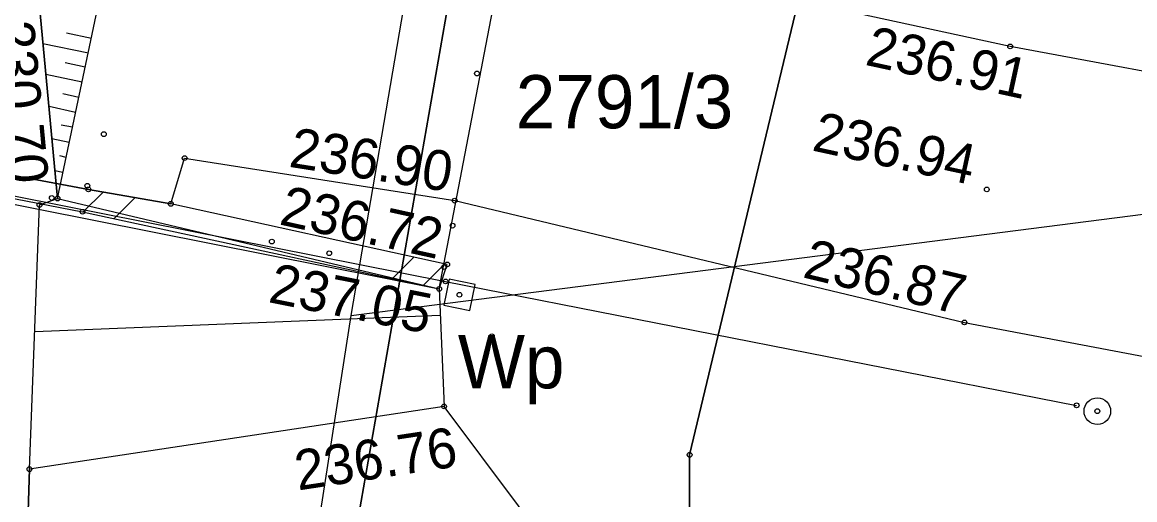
# Model space of a CAD drawing. Extents: x 6596400 to 6597200, y 5539751 to 5540251.
# Drawn here: x 6596740.59 to 6596761.51, y 5540079.28 to 5540088.25 of the extents above; entities that cross this region are included whole.
import ezdxf

# ---------------------------------------------------------------- set-up
doc = ezdxf.new("R2010")
doc.units = 0
for name, color, linetype in [('000 Inne (niezydentyfikowane)', 7, 'Continuous'), ('140-Punkty robocze', 7, 'Continuous'), ('203-punkt graniczny', 7, 'Continuous'), ('210-oznaczenie konturu użytku gruntowego', 7, 'Continuous'), ('211-numer działki ewidencyjnej', 7, 'Continuous'), ('218-kontur użytku gruntowego', 7, 'Continuous'), ('219-działka ewidencyjna', 7, 'Continuous'), ('bariera ochronna', 7, 'Continuous'), ('jezdnia', 7, 'Continuous'), ('Linia obszaru zagospodarowania terenu', 7, 'Continuous'), ('most', 7, 'Continuous'), ('pikieta sztuczna', 7, 'Continuous'), ('pikieta sztuczna-Atr2', 7, 'Continuous'), ('przewód telekomunikacyjny napowietrzny', 7, 'Continuous'), ('skarpa nieumocniona', 7, 'Continuous'), ('skarpa umocniona', 7, 'Continuous'), ('woda płynąca', 7, 'Continuous'), ('właz do komory lub kanału - kwadratowy', 7, 'Continuous'), ('właz do komory lub kanału - okrągły', 7, 'Continuous'), ('ściana oporowa (poligon)', 7, 'Continuous')]:
    doc.layers.add(name, color=color, linetype=linetype)

# ---------------------------------------------------------------- blocks, each defined once
blk = doc.blocks.new('203')
blk.add_circle((0, 0), 0.045)
blk = doc.blocks.new('SUTP')
for p, q in [((0, 0), (0.866, 0.5)), ((9.232, 0), (8.366, 0.5)), ((0, 0), (9.232, 0)), ((1.866, -0.5), (1, 0)), ((7.366, -0.5), (8.232, 0))]:
    blk.add_line(p, q)
blk = doc.blocks.new('US22A')
blk.add_lwpolyline([(-0.25, -0.25), (0.25, -0.25), (0.25, 0.25), (-0.25, 0.25)], close=True)
blk = doc.blocks.new('US22')
blk.add_circle((0, 0), 0.25)
blk = doc.blocks.new('PIKIETA')
blk.add_circle((0, 0), 0.045)
blk = doc.blocks.new('PW01')
blk.add_circle((0, 0), 0.045)

msp = doc.modelspace()

# ---------------------------------------------------------------- linework, layer by layer
at = {"layer": '000 Inne (niezydentyfikowane)'}
for points in [[(6596741.89, 5540087.95), (6596741.42, 5540088.05)], [(6596741.83, 5540087.67), (6596740.97, 5540087.85)], [(6596741.77, 5540087.41), (6596741.39, 5540087.49)], [(6596741.71, 5540087.13), (6596741.03, 5540087.27)], [(6596741.65, 5540086.84), (6596741.35, 5540086.91)], [(6596741.59, 5540086.56), (6596741.09, 5540086.67)], [(6596741.53, 5540086.28), (6596741.32, 5540086.32)], [(6596741.47, 5540085.99), (6596741.14, 5540086.06)], [(6596741.41, 5540085.71), (6596741.29, 5540085.74)], [(6596741.35, 5540085.43), (6596741.2, 5540085.46)], [(6596748.45, 5540082.74), (6596740.82, 5540082.43)]]:
    msp.add_lwpolyline(points, dxfattribs=at)
at = {"layer": '218-kontur użytku gruntowego'}
for points in [[(6596745.91, 5540073.23), (6596750.12, 5540097.31)], [(6596750.12, 5540097.31), (6596745.91, 5540073.23)], [(6596753.14, 5540080.12), (6596755.34, 5540089.31)], [(6596755.34, 5540089.31), (6596753.14, 5540080.12)], [(6596753.12, 5540074.2), (6596753.14, 5540080.12)], [(6596753.14, 5540080.12), (6596753.12, 5540074.2)]]:
    msp.add_lwpolyline(points, dxfattribs=at)
at = {"layer": '219-działka ewidencyjna'}
for points in [[(6596745.91, 5540073.23), (6596750.12, 5540097.31)], [(6596753.14, 5540080.12), (6596755.34, 5540089.31)], [(6596753.12, 5540074.2), (6596753.14, 5540080.12)]]:
    msp.add_lwpolyline(points, dxfattribs=at)
at = {"layer": 'bariera ochronna'}
msp.add_lwpolyline([(6596724.95, 5540083.06), (6596725.29, 5540087.8), (6596726.8, 5540087.69), (6596748.55, 5540083.38), (6596760.42, 5540081.05)], dxfattribs=at)
at = {"layer": 'jezdnia'}
for points in [[(6596653.124, 5540120.82), (6596653.79, 5540120.41), (6596660.56, 5540116.72), (6596663.8, 5540114.85), (6596668, 5540112.34), (6596669.54, 5540111.42), (6596675.97, 5540107.49), (6596679.93, 5540105.19), (6596682.35, 5540103.89), (6596691.43, 5540099.24), (6596702.2, 5540094.56), (6596706.34, 5540093.02), (6596710.59, 5540091.59), (6596715.92, 5540090.16), (6596720.02, 5540089.23), (6596724.29, 5540088.47), (6596726.93, 5540087.96), (6596734.57, 5540086.51), (6596738.41, 5540085.75), (6596741.83, 5540085.11), (6596743.38, 5540084.84), (6596743.64, 5540085.7), (6596748.72, 5540084.9)], [(6596828.719, 5540062.578), (6596825.42, 5540065.32), (6596821.78, 5540067.97), (6596818.46, 5540070.24), (6596813.26, 5540073.35), (6596810.44, 5540074.77), (6596805.94, 5540076.86), (6596804.14, 5540077.61), (6596801.52, 5540078.62), (6596798.28, 5540079.76), (6596795.16, 5540080.71), (6596792.67, 5540081.35), (6596788.77, 5540082.14), (6596786.6, 5540082.54), (6596777.46, 5540084.34), (6596768.21, 5540086.12), (6596759.17, 5540087.8), (6596749.8, 5540089.83), (6596749.82, 5540090.44), (6596743.18, 5540091.67), (6596739.76, 5540092.34), (6596735.83, 5540093.08), (6596728.26, 5540094.5), (6596723.35, 5540095.14)], [(6596748.72, 5540084.9), (6596758.31, 5540082.61), (6596767.09, 5540080.95), (6596776.43, 5540079.11), (6596785.57, 5540077.35), (6596790.64, 5540076.33), (6596793.76, 5540075.4), (6596796, 5540074.75), (6596799.11, 5540073.89), (6596802.37, 5540072.55), (6596804.34, 5540071.72), (6596806.42, 5540070.73), (6596808.2, 5540069.72), (6596810.28, 5540068.61), (6596812.76, 5540067.19), (6596815.5, 5540065.85), (6596818.95, 5540063.45), (6596822.11, 5540061.14), (6596825.559, 5540058.298)]]:
    msp.add_lwpolyline(points, dxfattribs=at)
at = {"layer": 'Linia obszaru zagospodarowania terenu'}
for points in [[(6596664.616, 5540132.112), (6596671.21, 5540127.95), (6596681.8, 5540121.54), (6596690.35, 5540115.69), (6596701.61, 5540105.97), (6596709.34, 5540098.61), (6596715.39, 5540091.82), (6596718.63, 5540088.53), (6596721.87, 5540084.71), (6596726.1, 5540083.21), (6596730.7, 5540082.79), (6596730.91, 5540075), (6596745.51, 5540074.64), (6596746.77, 5540082.74), (6596765.15, 5540085.09), (6596776.62, 5540086.27), (6596789.34, 5540086.1), (6596798.37, 5540085.54), (6596805.65, 5540083.56), (6596813.11, 5540081.53), (6596819.41, 5540077.54), (6596826.58, 5540072.81), (6596832.721, 5540067.998)], [(6596746.77, 5540082.74), (6596749.37, 5540097.92), (6596757.81, 5540103.76), (6596775.58, 5540097.4), (6596790.99, 5540107), (6596791.128, 5540108.731)]]:
    msp.add_lwpolyline(points, dxfattribs=at)
at = {"layer": 'most'}
msp.add_lwpolyline([(6596728.62, 5540094.88), (6596726.85, 5540087.53), (6596748.43, 5540083.24), (6596749.89, 5540090.85)], close=True, dxfattribs=at)
at = {"layer": 'skarpa nieumocniona'}
for points in [[(6596742.42, 5540096.36), (6596740.92, 5540088.42), (6596741.25, 5540084.94), (6596741.25, 5540084.94), (6596742.75, 5540092.05), (6596743.5, 5540096.22), (6596744.79, 5540102.47), (6596745.19, 5540106.93), (6596748.55, 5540109.04), (6596750.9, 5540110.05), (6596759.79, 5540109.57), (6596764.72, 5540107.7), (6596768.41, 5540103.97), (6596769.44, 5540104.84), (6596765.11, 5540108.34), (6596759.95, 5540110.31), (6596750.9, 5540111.08), (6596747.66, 5540110.25), (6596744.49, 5540107.55), (6596743.6, 5540103.66)], [(6596742.42, 5540096.36), (6596740.92, 5540088.42), (6596741.25, 5540084.94), (6596741.25, 5540084.94), (6596742.75, 5540092.05), (6596743.5, 5540096.22), (6596744.79, 5540102.47), (6596745.19, 5540106.93), (6596748.55, 5540109.04), (6596750.9, 5540110.05), (6596759.79, 5540109.57), (6596764.72, 5540107.7), (6596768.41, 5540103.97), (6596769.44, 5540104.84), (6596765.11, 5540108.34), (6596759.95, 5540110.31), (6596750.9, 5540111.08), (6596747.66, 5540110.25), (6596744.49, 5540107.55), (6596743.6, 5540103.66)], [(6596756.22, 5540066.9), (6596754.09, 5540066.07), (6596752.07, 5540067.76), (6596750.47, 5540074), (6596751.32, 5540077.29), (6596748.52, 5540081.03), (6596740.72, 5540079.85), (6596740.68, 5540078.45), (6596742.94, 5540074), (6596746.51, 5540071.34), (6596747.03, 5540064.86), (6596756.25, 5540062.4), (6596756.95, 5540064.41)], [(6596756.22, 5540066.9), (6596754.09, 5540066.07), (6596752.07, 5540067.76), (6596750.47, 5540074), (6596751.32, 5540077.29), (6596748.52, 5540081.03), (6596740.72, 5540079.85), (6596740.68, 5540078.45), (6596742.94, 5540074), (6596746.51, 5540071.34), (6596747.03, 5540064.86), (6596756.25, 5540062.4), (6596756.95, 5540064.41)]]:
    msp.add_lwpolyline(points, close=True, dxfattribs=at)
at = {"layer": 'skarpa umocniona'}
msp.add_lwpolyline([(6596748.43, 5540083.24), (6596748.52, 5540081.03), (6596740.72, 5540079.85), (6596740.91, 5540084.82), (6596741.25, 5540084.94)], close=True, dxfattribs=at)
msp.add_lwpolyline([(6596748.43, 5540083.24), (6596748.52, 5540081.03), (6596740.72, 5540079.85), (6596740.91, 5540084.82), (6596741.25, 5540084.94)], close=True, dxfattribs=at)
at = {"layer": 'woda płynąca'}
msp.add_lwpolyline([(6596746.88, 5540042.02), (6596743.2, 5540046.89), (6596742.01, 5540050.53), (6596741.65, 5540054.82), (6596742.47, 5540061.97), (6596743.25, 5540066.3), (6596741.68, 5540074.92), (6596740.68, 5540078.45), (6596740.72, 5540079.85), (6596740.91, 5540084.82), (6596741.25, 5540084.94), (6596740.92, 5540088.42), (6596742.42, 5540096.36), (6596743.6, 5540103.66), (6596744.49, 5540107.55), (6596747.66, 5540110.25), (6596750.9, 5540111.08), (6596759.95, 5540110.31), (6596765.11, 5540108.34), (6596769.44, 5540104.84), (6596775.99, 5540100.07), (6596783.39, 5540096.06), (6596790.43, 5540094.51)], dxfattribs=at)
at = {"layer": 'ściana oporowa (poligon)'}
msp.add_lwpolyline([(6596748.43, 5540083.24), (6596748.58, 5540083.7), (6596743.38, 5540084.84), (6596741.83, 5540085.11), (6596738.41, 5540085.75), (6596734.57, 5540086.51), (6596726.93, 5540087.96), (6596726.85, 5540087.53), (6596734.45, 5540086.08), (6596738.35, 5540085.34), (6596741.72, 5540084.69)], close=True, dxfattribs=at)
msp.add_lwpolyline([(6596748.43, 5540083.24), (6596748.58, 5540083.7), (6596743.38, 5540084.84), (6596741.83, 5540085.11), (6596738.41, 5540085.75), (6596734.57, 5540086.51), (6596726.93, 5540087.96), (6596726.85, 5540087.53), (6596734.45, 5540086.08), (6596738.35, 5540085.34), (6596741.72, 5540084.69)], close=True, dxfattribs=at)
for points in [[(6596741.732, 5540084.687), (6596742.107, 5540085.062)], [(6596742.314, 5540084.562), (6596742.709, 5540084.957)], [(6596747.547, 5540083.431), (6596747.953, 5540083.837)], [(6596748.128, 5540083.305), (6596748.533, 5540083.71)]]:
    msp.add_lwpolyline(points, dxfattribs=at)

# ---------------------------------------------------------------- block references
at = {"layer": '140-Punkty robocze'}
for p in [(6596749.14, 5540087.29), (6596742.12, 5540086.15), (6596743.64, 5540085.7), (6596741.81, 5540085.18), (6596741.83, 5540085.11), (6596741.14, 5540084.95), (6596741.25, 5540084.94), (6596740.91, 5540084.82), (6596741.72, 5540084.69), (6596743.38, 5540084.84), (6596748.68, 5540084.43), (6596745.28, 5540084.13), (6596746.36, 5540083.91), (6596748.52, 5540083.65), (6596748.55, 5540083.38), (6596748.81, 5540083.13), (6596749.42, 5540082.35), (6596760.42, 5540081.05), (6596760.81, 5540080.94), (6596740.72, 5540079.85)]:
    msp.add_blockref('PIKIETA', p, dxfattribs=at)
at = {"layer": '203-punkt graniczny'}
msp.add_blockref('203', (6596753.14, 5540080.12), dxfattribs=at)
at = {"layer": 'pikieta sztuczna'}
for p in [(6596759.17, 5540087.8), (6596758.73, 5540085.11), (6596748.72, 5540084.9), (6596748.58, 5540083.7), (6596748.43, 5540083.24), (6596758.31, 5540082.61), (6596748.52, 5540081.03)]:
    msp.add_blockref('PW01', p, dxfattribs=at)
at = {"layer": 'przewód telekomunikacyjny napowietrzny', "rotation": -11.666000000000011}
msp.add_blockref('SUTP', (6596759.96, 5540090.03), dxfattribs=at)
at = {"layer": 'właz do komory lub kanału - kwadratowy', "rotation": -11.802000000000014}
msp.add_blockref('US22A', (6596748.81, 5540083.13), dxfattribs=at)
at = {"layer": 'właz do komory lub kanału - okrągły'}
msp.add_blockref('US22', (6596760.81, 5540080.94), dxfattribs=at)

# ---------------------------------------------------------------- texts
at = {"layer": '210-oznaczenie konturu użytku gruntowego'}
msp.add_text('Wp', height=1, dxfattribs=at).set_placement((6596748.78, 5540081.37))
at = {"layer": '211-numer działki ewidencyjnej'}
msp.add_text('2791/3', height=1, dxfattribs=at).set_placement((6596749.87, 5540086.26))
at = {"layer": 'pikieta sztuczna-Atr2'}
for s, rotation, p in [('230.70', 275.417, (6596740.053, 5540088.249)), ('236.91', 347.776, (6596756.421, 5540087.457)), ('236.94', 347.776, (6596755.421, 5540085.847)), ('236.90', 351.051, (6596745.583, 5540085.539)), ('236.72', 347.635, (6596745.399, 5540084.457)), ('236.87', 346.57, (6596755.246, 5540083.461)), ('237.05', 348.756, (6596745.194, 5540082.994)), ('236.76', 8.603, (6596745.772, 5540079.448))]:
    msp.add_text(s, height=0.75, rotation=rotation, dxfattribs=at).set_placement(p)

doc.saveas('drawing.dxf')
